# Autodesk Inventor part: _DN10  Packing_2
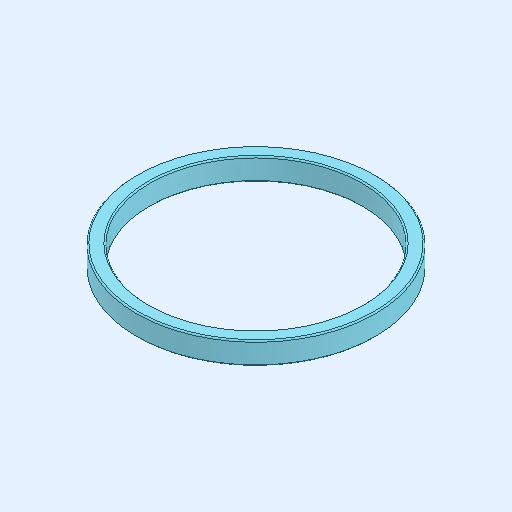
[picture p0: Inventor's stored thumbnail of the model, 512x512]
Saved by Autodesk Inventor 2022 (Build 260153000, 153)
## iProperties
Created: 2021-12
Part Number: _DN10  Packing_2
Material: Generico
Document SubType Name: Modeling
Designer: admin
Density: 1 g/cm^3
Appearance: Default
Author: admin
Revision Number: NONE
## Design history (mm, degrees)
feature "_DN10  Packing"
node "Solido1"
